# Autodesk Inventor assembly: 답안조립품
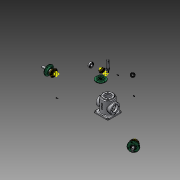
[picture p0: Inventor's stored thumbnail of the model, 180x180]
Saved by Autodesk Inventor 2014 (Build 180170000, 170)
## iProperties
Created: 2015-10
Part Number: 답안조립품
Document SubType Name: Assembly
Designer: Administrator
Author: Administrator
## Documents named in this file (14)
- C:\Users\Administrator\Desktop\451007V1020\답안조립품.iam
- C:\Users\Administrator\Desktop\451007V1020\1-본체.ipt
- C:\Users\Administrator\Desktop\451007V1020\M4.ipt
- C:\Users\Administrator\Desktop\451007V1020\메인 베벨기어.ipt
- C:\Users\Administrator\Desktop\451007V1020\메인 축.ipt
- 메인 축.ipt
- C:\Users\Administrator\Desktop\451007V1020\베어링 6203.ipt
- C:\Users\Administrator\Desktop\451007V1020\서브 베벨기어.ipt
- C:\Users\Administrator\Desktop\451007V1020\서브 축.ipt
- 서브 축.ipt
- C:\Users\Administrator\Desktop\451007V1020\오일실.ipt
- C:\Users\Administrator\Desktop\451007V1020\커버.ipt
- C:\Users\Administrator\Desktop\451007V1020\키 4x4.ipt
- C:\Users\Administrator\Desktop\451007V1020\키 5x5.ipt
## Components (2 placed, 2 different names)
1. 1-본체:1
2. M4:1
## Named parameters: d16_d3 = 0, d17_d4 = 0, d18_d5 = 0, d19_d6 = 0, d20_d7 = 0, d21_d9 = 0, d22_d10 = 0, d23_d11 = 0, d24_d12 = 0, d25_d13 = 0, d26_d14 = 0, d27_d15 = 0
